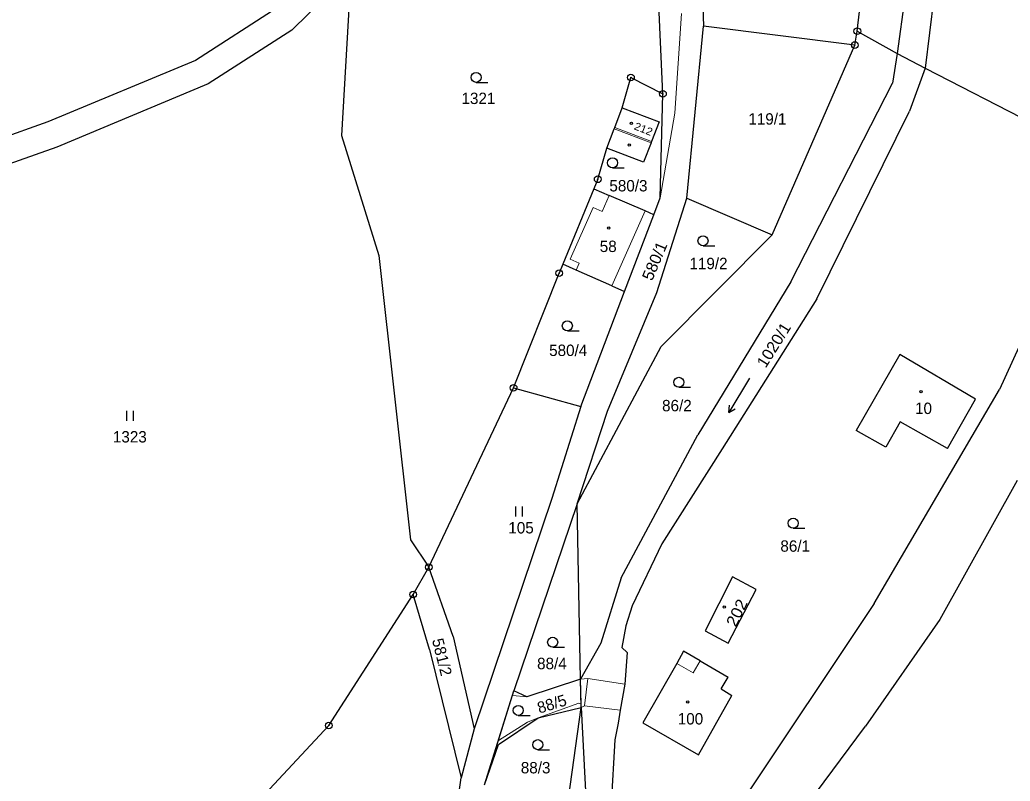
# Model space of a CAD drawing. Extents: x -601131 to -597152, y -1058536 to -1055911.
# Drawn here: x -599499.1 to -599351.3, y -1056748.4 to -1056634.8 of the extents above; entities that cross this region are included whole.
import ezdxf
from ezdxf.enums import TextEntityAlignment as Align

# ---------------------------------------------------------------- set-up
doc = ezdxf.new("R2010")
doc.units = 0
doc.header["$LTSCALE"] = 0.68
for name, color, linetype, lineweight in [('1', 7, 'Continuous', 25), ('13', 7, 'Continuous', 13), ('3', 7, 'Continuous', 25), ('4', 7, 'Continuous', 13), ('5', 7, 'Continuous', 25), ('8', 7, 'Continuous', 25)]:
    doc.layers.add(name, color=color, linetype=linetype, lineweight=lineweight)
doc.layers.add('2', color=7, linetype='Continuous')

msp = doc.modelspace()

# ---------------------------------------------------------------- linework, layer by layer
at = {"layer": '1'}
for p, q in [((-599374.11, -1056636.47), (-599370.69, -1056605.29)), ((-599397.87, -1056607.43), (-599397.08, -1056635.71)), ((-599366.33, -1056626.58), (-599368.17, -1056639.78)), ((-599449.68, -1056627.67), (-599458.47, -1056636.3)), ((-599449.68, -1056627.67), (-599451.05, -1056652.02)), ((-599362.14, -1056627.07), (-599364, -1056641.99)), ((-599403.11, -1056645.83), (-599403.77, -1056631.22)), ((-599460.68, -1056633), (-599472.84, -1056640.82)), ((-599458.47, -1056636.3), (-599470.94, -1056644.34)), ((-599399.53, -1056661.41), (-599397.08, -1056635.71)), ((-599374.49, -1056638.54), (-599397.08, -1056635.71)), ((-599374.49, -1056638.54), (-599374.11, -1056636.47)), ((-599374.11, -1056636.47), (-599368.17, -1056639.78)), ((-599386.8, -1056666.88), (-599374.49, -1056638.54)), ((-599368.17, -1056639.78), (-599368.88, -1056644.24)), ((-599368.17, -1056639.78), (-599364, -1056641.99)), ((-599472.84, -1056640.82), (-599494.87, -1056650.02)), ((-599364, -1056641.99), (-599366.34, -1056648.39)), ((-599364, -1056641.99), (-599337.39, -1056655.67)), ((-599470.94, -1056644.34), (-599493.54, -1056653.79)), ((-599409.21, -1056647.91), (-599407.89, -1056643.37)), ((-599407.89, -1056643.37), (-599403.11, -1056645.83)), ((-599384.01, -1056673.9), (-599368.88, -1056644.24)), ((-599403.53, -1056661.32), (-599403.11, -1056645.83)), ((-599380.15, -1056676.39), (-599366.34, -1056648.39)), ((-599494.87, -1056650.02), (-599514.44, -1056656.97)), ((-599403.68, -1056650), (-599404.83, -1056652.93)), ((-599410.38, -1056651.02), (-599410.31, -1056650.83)), ((-599451.05, -1056652.02), (-599445.48, -1056669.95)), ((-599404.89, -1056653.13), (-599406.02, -1056656.03)), ((-599404.83, -1056652.93), (-599404.89, -1056653.13)), ((-599493.54, -1056653.79), (-599513.66, -1056660.89)), ((-599412.84, -1056658.57), (-599411.47, -1056653.92)), ((-599337.39, -1056655.67), (-599352.88, -1056689.93)), ((-599412.84, -1056658.57), (-599413.43, -1056660)), ((-599413.43, -1056660), (-599418.04, -1056671.25)), ((-599413.43, -1056660), (-599411.14, -1056660.99)), ((-599405.78, -1056663.3), (-599411.14, -1056660.99)), ((-599404.49, -1056663.86), (-599403.53, -1056661.32)), ((-599404.01, -1056675.49), (-599399.53, -1056661.41)), ((-599399.53, -1056661.41), (-599386.8, -1056666.88)), ((-599404.49, -1056663.86), (-599405.78, -1056663.3)), ((-599408.84, -1056675.32), (-599404.49, -1056663.86)), ((-599403.36, -1056683.53), (-599386.8, -1056666.88)), ((-599445.48, -1056669.95), (-599440.76, -1056712.38)), ((-599425.39, -1056689.7), (-599418.59, -1056672.58)), ((-599418.04, -1056671.25), (-599418.59, -1056672.58)), ((-599416.07, -1056672.12), (-599418.04, -1056671.25)), ((-599410.76, -1056674.47), (-599416.07, -1056672.12)), ((-599384.01, -1056673.9), (-599397.91, -1056696.7)), ((-599415.35, -1056692.49), (-599408.84, -1056675.32)), ((-599411.4, -1056693.16), (-599404.01, -1056675.49)), ((-599410.76, -1056674.47), (-599408.84, -1056675.32)), ((-599415.89, -1056706.99), (-599403.36, -1056683.53)), ((-599367.78, -1056684.7), (-599374.3, -1056696.06)), ((-599356.47, -1056691.4), (-599367.78, -1056684.7)), ((-599438.04, -1056716.46), (-599425.39, -1056689.7)), ((-599425.39, -1056689.7), (-599415.35, -1056692.49)), ((-599371.62, -1056721.87), (-599352.88, -1056689.93)), ((-599360.64, -1056698.77), (-599356.47, -1056691.4)), ((-599415.35, -1056692.49), (-599419.68, -1056706.2)), ((-599415.89, -1056706.99), (-599411.4, -1056693.16)), ((-599369.85, -1056698.57), (-599374.3, -1056696.06)), ((-599367.7, -1056694.78), (-599369.85, -1056698.57)), ((-599360.64, -1056698.77), (-599367.7, -1056694.78)), ((-599409.34, -1056718.06), (-599397.91, -1056696.7)), ((-599350.26, -1056703.54), (-599361.8, -1056724.28)), ((-599419.68, -1056706.2), (-599431.28, -1056740.6)), ((-599415.89, -1056706.99), (-599425.35, -1056734.91)), ((-599415.39, -1056733.16), (-599415.89, -1056706.99)), ((-599440.76, -1056712.38), (-599438.04, -1056716.46)), ((-599403.26, -1056713), (-599407.7, -1056722.23)), ((-599440.38, -1056720.54), (-599438.04, -1056716.46)), ((-599434.4, -1056726.83), (-599438.04, -1056716.46)), ((-599409.34, -1056718.06), (-599412.4, -1056727.81)), ((-599452.95, -1056740.08), (-599440.38, -1056720.54)), ((-599437.96, -1056728.75), (-599440.38, -1056720.54)), ((-599371.62, -1056721.87), (-599413.52, -1056784.73)), ((-599407.7, -1056722.23), (-599408.66, -1056725.2)), ((-599361.8, -1056724.28), (-599372.87, -1056740.17)), ((-599408.66, -1056725.2), (-599409.24, -1056728.45)), ((-599434.4, -1056726.83), (-599431.28, -1056740.6)), ((-599437.96, -1056728.75), (-599433.23, -1056747.88)), ((-599412.4, -1056727.81), (-599415.39, -1056733.16)), ((-599409.24, -1056728.45), (-599408.45, -1056729.2)), ((-599408.45, -1056729.2), (-599408.82, -1056733.91)), ((-599400.02, -1056729), (-599401.06, -1056730.82)), ((-599397.55, -1056730.44), (-599400.02, -1056729)), ((-599401.06, -1056730.82), (-599406.13, -1056739.67)), ((-599397.55, -1056730.44), (-599393.4, -1056732.86)), ((-599415.39, -1056733.16), (-599423.4, -1056735.81)), ((-599415.29, -1056737.38), (-599415.39, -1056733.16)), ((-599394.44, -1056734.64), (-599393.4, -1056732.86)), ((-599408.82, -1056733.91), (-599409.49, -1056737.8)), ((-599394.44, -1056734.64), (-599392.81, -1056735.59)), ((-599429.72, -1056748.92), (-599425.35, -1056734.91)), ((-599423.4, -1056735.81), (-599425.35, -1056734.91)), ((-599397.81, -1056744.48), (-599392.81, -1056735.59)), ((-599421.72, -1056738.94), (-599415.29, -1056737.38)), ((-599417.21, -1056750.96), (-599415.29, -1056737.38)), ((-599415.29, -1056737.38), (-599414.02, -1056763.41)), ((-599427.64, -1056742.94), (-599421.72, -1056738.94)), ((-599409.49, -1056737.8), (-599409.8, -1056739.74)), ((-599467.12, -1056755.26), (-599452.95, -1056740.08)), ((-599409.8, -1056739.74), (-599410.27, -1056742.24)), ((-599406.13, -1056739.67), (-599397.81, -1056744.48)), ((-599392.52, -1056766.52), (-599372.87, -1056740.17)), ((-599431.28, -1056740.6), (-599433.23, -1056747.88)), ((-599429.72, -1056748.92), (-599427.64, -1056742.94)), ((-599410.27, -1056742.24), (-599410.86, -1056752.01)), ((-599434.8, -1056758.96), (-599433.23, -1056747.88))]:
    msp.add_line(p, q, dxfattribs=at)
for points in [[(-599410.31, -1056650.83), (-599409.21, -1056647.91), (-599403.68, -1056650)], [(-599406.02, -1056656.03), (-599411.47, -1056653.92), (-599410.38, -1056651.02)], [(-599380.15, -1056676.39), (-599394.29, -1056698.79), (-599403.26, -1056713)]]:
    msp.add_lwpolyline(points, dxfattribs=at)
msp.add_lwpolyline([(-599389.22, -1056719.78), (-599392.75, -1056717.9), (-599396.82, -1056725.96), (-599393.39, -1056727.79)], close=True, dxfattribs=at)
at = {"layer": '13'}
msp.add_lwpolyline([(-599415.3, -1056736.9), (-599415.39, -1056733.16), (-599423.4, -1056735.81), (-599425.57, -1056735.61), (-599427.67, -1056742.35), (-599423.32, -1056739.57), (-599421.72, -1056738.94), (-599415.65, -1056736.74)], close=True, dxfattribs=at)
at = {"layer": '3'}
for p, q in [((-599430.993, -1056644.11), (-599429.243, -1056644.11)), ((-599410.623, -1056656.86), (-599408.873, -1056656.86)), ((-599397.133, -1056668.49), (-599395.383, -1056668.49)), ((-599417.373, -1056681.2), (-599415.623, -1056681.2)), ((-599400.743, -1056689.62), (-599398.993, -1056689.62)), ((-599483.121, -1056694.62), (-599483.121, -1056693.12)), ((-599482.12, -1056694.62), (-599482.12, -1056693.12)), ((-599393.271, -1056693.392), (-599393.198, -1056692.296)), ((-599425.071, -1056708.91), (-599425.071, -1056707.41)), ((-599424.07, -1056708.91), (-599424.07, -1056707.41)), ((-599383.683, -1056710.66), (-599381.933, -1056710.66)), ((-599419.563, -1056728.41), (-599417.813, -1056728.41)), ((-599424.693, -1056738.58), (-599422.943, -1056738.58)), ((-599421.793, -1056743.7), (-599420.043, -1056743.7))]:
    msp.add_line(p, q, dxfattribs=at)
msp.add_lwpolyline([(-599390.181, -1056688.249), (-599393.271, -1056693.392), (-599392.338, -1056692.812)], dxfattribs=at)
for centre in [(-599430.9929, -1056643.3598), (-599410.6229, -1056656.1098), (-599397.1329, -1056667.7398), (-599417.3729, -1056680.4498), (-599400.7429, -1056688.8698), (-599383.6829, -1056709.9098), (-599419.5629, -1056727.6598), (-599424.6929, -1056737.8298), (-599421.7929, -1056742.9498)]:
    msp.add_circle(centre, 0.75, dxfattribs=at)
at = {"layer": '4'}
for p, q in [((-599401.33, -1056648.71), (-599400.35, -1056633.83)), ((-599403.53, -1056661.32), (-599401.33, -1056648.71)), ((-599410.38, -1056651.02), (-599404.89, -1056653.13)), ((-599404.83, -1056652.93), (-599410.31, -1056650.83)), ((-599411.14, -1056660.99), (-599412.2, -1056663.38)), ((-599413.54, -1056662.78), (-599416.94, -1056670.48)), ((-599412.2, -1056663.38), (-599413.54, -1056662.78)), ((-599405.78, -1056663.3), (-599410.76, -1056674.47)), ((-599416.94, -1056670.48), (-599415.6, -1056671.07)), ((-599415.6, -1056671.07), (-599416.07, -1056672.12)), ((-599398.58, -1056732.24), (-599401.06, -1056730.82)), ((-599398.58, -1056732.24), (-599397.55, -1056730.44)), ((-599414.83, -1056737.13), (-599414.31, -1056733.08)), ((-599414.83, -1056737.13), (-599415.29, -1056737.38)), ((-599414.83, -1056737.13), (-599409.49, -1056737.8))]:
    msp.add_line(p, q, dxfattribs=at)
msp.add_lwpolyline([(-599415.39, -1056733.16), (-599414.31, -1056733.08), (-599408.82, -1056733.91)], dxfattribs=at)
at = {"layer": '5'}
for centre in [(-599407.8068, -1056650.2192), (-599408.1268, -1056653.4592), (-599411.1868, -1056665.8592), (-599364.6068, -1056690.2692), (-599393.9668, -1056722.4192), (-599399.4068, -1056736.5692)]:
    msp.add_circle(centre, 0.175, dxfattribs=at)
at = {"layer": '8'}
for centre, radius in [((-599374.11, -1056636.4699), 0.5), ((-599374.11, -1056636.4699), 0.0303), ((-599374.49, -1056638.5399), 0.5), ((-599374.49, -1056638.5399), 0.0303), ((-599407.89, -1056643.3699), 0.5), ((-599407.89, -1056643.3699), 0.0303), ((-599403.11, -1056645.8299), 0.5), ((-599403.11, -1056645.8299), 0.0303), ((-599412.84, -1056658.5699), 0.5), ((-599412.84, -1056658.5699), 0.0303), ((-599418.59, -1056672.5799), 0.5), ((-599418.59, -1056672.5799), 0.0303), ((-599425.39, -1056689.6999), 0.5), ((-599425.39, -1056689.6999), 0.0303), ((-599438.04, -1056716.4599), 0.5), ((-599438.04, -1056716.4599), 0.0303), ((-599440.38, -1056720.5399), 0.5), ((-599440.38, -1056720.5399), 0.0303), ((-599452.95, -1056740.0799), 0.5), ((-599452.95, -1056740.0799), 0.0303)]:
    msp.add_circle(centre, radius, dxfattribs=at)

# ---------------------------------------------------------------- texts
at = {"layer": '2'}
for s, p in [('1321', (-599430.64, -1056647.342)), ('580/3', (-599408.26, -1056660.385)), ('1323', (-599482.65, -1056697.852))]:
    msp.add_text(s, height=1.7, dxfattribs=at).set_placement(p, align=Align.CENTER)
for s, p in [('119/1', (-599390.37, -1056650.415)), ('58', (-599412.54, -1056669.425)), ('119/2', (-599399.16, -1056671.985)), ('580/4', (-599420.09, -1056684.945)), ('86/2', (-599403.24, -1056693.195)), ('10', (-599365.5, -1056693.604)), ('105', (-599426.18, -1056711.425)), ('86/1', (-599385.59, -1056714.155)), ('88/4', (-599421.89, -1056731.685)), ('100', (-599400.9, -1056739.935)), ('88/3', (-599424.32, -1056747.235))]:
    msp.add_text(s, height=1.7, dxfattribs=at).set_placement(p)
at = {"layer": '2', "width": 1.1}
for s, height, rotation, p in [('212', 1.139, 338, (-599406.2278, -1056651.5974)), ('202', 1.7, 64, (-599391.3245, -1056723.6356))]:
    msp.add_text(s, height=height, rotation=rotation, dxfattribs=at).set_placement(p, align=Align.CENTER)
at = {"layer": '2', "width": 1.05}
for s, rotation, p in [('580/1', 67, (-599404.738, -1056673.846)), ('1020/1', 58, (-599387.789, -1056686.845))]:
    msp.add_text(s, height=1.7, rotation=rotation, dxfattribs=at).set_placement(p)
at = {"layer": '2'}
msp.add_text('581/2', height=1.7, rotation=284, dxfattribs=at).set_placement((-599437.582, -1056727.322))
msp.add_text('88/5', height=1.7, rotation=17, dxfattribs=at).set_placement((-599419.439, -1056737.6774), align=Align.CENTER)

doc.saveas('drawing.dxf')
